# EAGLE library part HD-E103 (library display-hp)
LED DISPLAY 1-character 7 segment, decimal point right
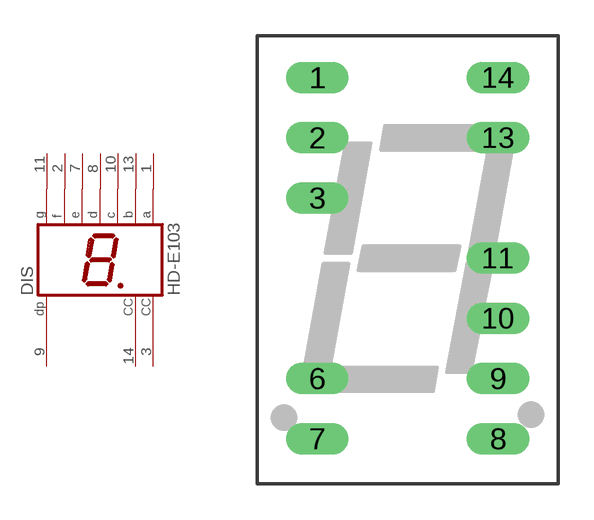
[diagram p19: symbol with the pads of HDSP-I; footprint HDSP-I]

Designator prefix DIS

## HD-E103 (OC_FARNELL: unknown; OC_NEWARK: unknown)  [HDSP-I]
1  A  pas
2  F  pas
3  CC  pas
7  E  pas
8  D  pas
9  DP  pas
10  C  pas
11  G  pas
13  B  pas
14  CC  pas

## Footprint HDSP-I (pad centres in mm)
LED DISPLAY 12-mm 1 character 7 segment, 2 decimal points
drill 0.813 long: 1 -3.81,7.62; 2 -3.81,5.08; 3 -3.81,2.54; 6 -3.81,-5.08; 7 -3.81,-7.62; 8 3.81,-7.62; 9 3.81,-5.08; 10 3.81,-2.54; 11 3.81,0; 13 3.81,5.08; 14 3.81,7.62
